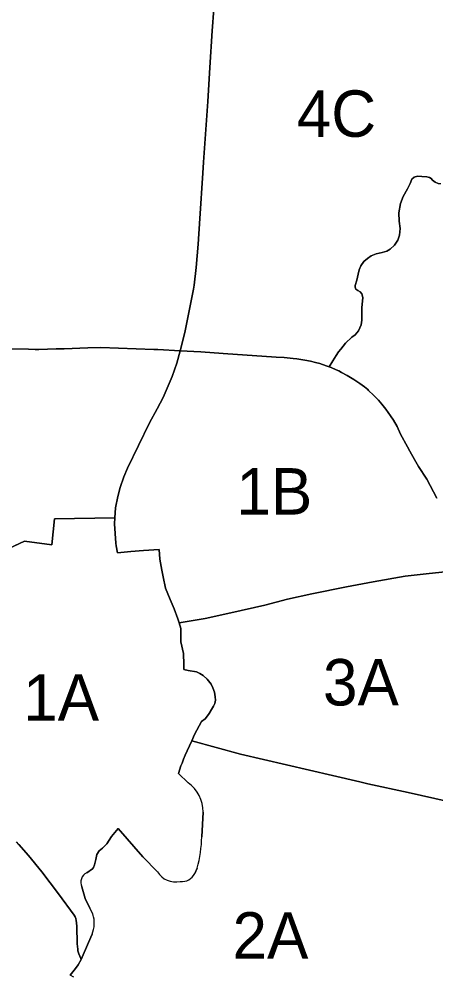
# Model space of a CAD drawing. Extents: x 152750 to 166250, y 378996 to 390000.
# Drawn here: x 161080 to 162877, y 382190 to 386288 of the extents above; entities that cross this region are included whole.
import ezdxf

# ---------------------------------------------------------------- set-up
doc = ezdxf.new("R2010")
doc.units = 0
doc.layers.add('BLT_Nummers', color=7, linetype='Continuous')
doc.layers.add('BLT_Shapes', color=7, linetype='Continuous')

msp = doc.modelspace()

# ---------------------------------------------------------------- linework, layer by layer
at = {"layer": 'BLT_Shapes'}
for p, q in [((161912.3, 386237.6), (161902.1, 386079.3)), ((161902.1, 386079.3), (161893.7, 385933.6)), ((161893.7, 385933.6), (161875.4, 385672.6)), ((162797.2, 385611.8), (162815.3, 385610.1)), ((162861.9, 385595), (162872.7, 385586.3)), ((162723.7, 385493.9), (162735, 385524.1)), ((162716, 385453.7), (162723.7, 385493.9)), ((161859.1, 385428.7), (161851.8, 385318.4)), ((162718.1, 385418.2), (162716, 385453.7)), ((162721.6, 385386.3), (162718.1, 385418.2)), ((162719, 385358.2), (162721.6, 385386.3)), ((162545.3, 385209.1), (162553.1, 385225.5)), ((162553.1, 385225.5), (162565.6, 385244.1)), ((162540.6, 385190.5), (162545.3, 385209.1)), ((161831.9, 385125.3), (161794.2, 384939.2)), ((162560.9, 385089), (162557, 385105)), ((162554.4, 384971.9), (162556.6, 384992.2)), ((161794.2, 384939.2), (161773.9, 384860.2)), ((162513.4, 384918.7), (162528.1, 384928.3)), ((161149.4, 384865.5), (161165.2, 384865.5)), ((161165.2, 384865.5), (161239.4, 384868)), ((161239.4, 384868), (161274.7, 384868.9)), ((161274.7, 384868.9), (161375.8, 384873)), ((161375.8, 384873), (161432.8, 384873.7)), ((162416, 384790.8), (162432.8, 384816.1)), ((162569.1, 384704.2), (162582.5, 384693.2)), ((162582.5, 384693.2), (162586.4, 384689.7)), ((162643.8, 384630.1), (162661.1, 384608.1)), ((162661.1, 384608.1), (162680.5, 384580.4)), ((162709, 384534.6), (162723.7, 384501.6)), ((162764.3, 384427.5), (162783.5, 384391.8)), ((161515.4, 384271.4), (161531.5, 384317.1)), ((161232.4, 384136.5), (161492.7, 384141)), ((161492.7, 384141), (161491, 384114.6)), ((160881.5, 383937.4), (161102.9, 384039.9)), ((161498.3, 384019.9), (161504.2, 383989.9)), ((161504.2, 383989.9), (161561.8, 383996.2)), ((161561.8, 383996.2), (161616.9, 383999.8)), ((161616.9, 383999.8), (161684, 384004.2)), ((162341.5, 383813.6), (162236.2, 383790.4)), ((161763.7, 383706), (161769.3, 383688.6)), ((161769.3, 383688.6), (161777.2, 383664.4)), ((161788.4, 383557.5), (161790.7, 383508.9)), ((161923.1, 383342.4), (161917.7, 383329.6)), ((161866.6, 383264.3), (161836, 383207.9)), ((161836, 383207.9), (161824.5, 383181.5)), ((161824.5, 383181.5), (162034.4, 383123.8)), ((161795.8, 383119.3), (161789.1, 383101.9)), ((161809.4, 383000.4), (161766.8, 383040)), ((161766.8, 383040), (161809.4, 383000.4)), ((162548.9, 383003.9), (162582.8, 382996)), ((162582.8, 382996), (162756.1, 382958.4)), ((161867.4, 382768.3), (161873.2, 382874.7)), ((161873.2, 382874.7), (161867.4, 382768.3)), ((161506.9, 382803.7), (161477.9, 382768.9)), ((161477.9, 382768.9), (161457.6, 382738)), ((161457.6, 382738), (161439.2, 382719.6)), ((161177.8, 382617.1), (161121.2, 382688.1)), ((161396.7, 382629.7), (161371.5, 382613.2)), ((161401.5, 382635.5), (161396.7, 382629.7)), ((161837.4, 382609.8), (161848, 382633)), ((161848, 382633), (161837.4, 382609.8)), ((161249.4, 382522.2), (161177.8, 382617.1)), ((161385.1, 382460.5), (161398.6, 382434.4)), ((161345.7, 382244.2), (161337.1, 382264.8)), ((161335.4, 382216.2), (161348, 382239.7)), ((161347.7, 382240.2), (161345.7, 382244.2)), ((161348, 382239.7), (161347.7, 382240.2)), ((161323.9, 382201.5), (161335.4, 382216.2))]:
    msp.add_line(p, q, dxfattribs=at)
for points in [[(161773.9, 384860.2), (161794.2, 384939.2), (161831.9, 385125.3), (161835, 385142.9), (161843.4, 385219.2), (161851.8, 385318.4), (161859.1, 385428.7), (161872.2, 385624.7), (161875.4, 385672.6), (161893.7, 385933.6), (161902.1, 386079.3), (161912.3, 386237.6), (161927.2, 386428.6), (161929.6, 386454.8), (161933.9, 386510.6)], [(161933.9, 386510.6), (161929.6, 386454.8), (161927.2, 386428.6), (161912.3, 386237.6)], [(161875.4, 385672.6), (161872.2, 385624.7), (161859.1, 385428.7)], [(162885.7, 385580.3), (162872.7, 385586.3), (162861.9, 385595), (162855.5, 385601), (162848.1, 385606.2), (162836.5, 385609.2), (162815.3, 385610.1), (162797.2, 385611.8), (162782, 385607.1), (162772.1, 385598.4), (162764.8, 385580.7), (162753.5, 385556.9), (162735, 385524.1), (162723.7, 385493.9), (162716, 385453.7), (162718.1, 385418.2), (162721.6, 385386.3), (162719, 385358.2), (162712.5, 385336.1), (162697.8, 385314.1), (162679.7, 385296.8), (162664.6, 385288.2), (162644.3, 385283.4), (162618.3, 385277), (162597.6, 385268.7), (162581.6, 385257.9), (162565.6, 385244.1), (162553.1, 385225.5), (162545.3, 385209.1), (162540.6, 385190.5), (162535.8, 385163.7), (162528.1, 385141.7), (162528.1, 385133.9), (162531.1, 385124.9), (162539.3, 385118.8), (162549.7, 385113.6), (162557, 385105), (162560.9, 385089), (162557.4, 385044.9), (162556.6, 384992.2), (162554.4, 384971.9), (162543.2, 384946.4), (162528.1, 384928.3), (162513.4, 384918.7), (162486.6, 384892.4), (162466.3, 384867.5), (162456.6, 384855.9), (162447.1, 384840.3), (162432.8, 384816.1), (162416, 384790.8)], [(162735, 385524.1), (162753.5, 385556.9), (162764.8, 385580.7), (162772.1, 385598.4)], [(162772.1, 385598.4), (162782, 385607.1), (162797.2, 385611.8)], [(162815.3, 385610.1), (162836.5, 385609.2), (162848.1, 385606.2), (162855.5, 385601), (162861.9, 385595)], [(162872.7, 385586.3), (162885.7, 385580.3), (162896.9, 385580.7)], [(162679.7, 385296.8), (162697.8, 385314.1), (162712.5, 385336.1), (162719, 385358.2)], [(161851.8, 385318.4), (161843.4, 385219.2), (161835, 385142.9), (161831.9, 385125.3)], [(162618.3, 385277), (162644.3, 385283.4), (162664.6, 385288.2), (162679.7, 385296.8)], [(162565.6, 385244.1), (162581.6, 385257.9), (162597.6, 385268.7), (162618.3, 385277)], [(162528.1, 385133.9), (162528.1, 385141.7), (162535.8, 385163.7), (162540.6, 385190.5)], [(162557, 385105), (162549.7, 385113.6), (162539.3, 385118.8), (162531.1, 385124.9), (162528.1, 385133.9)], [(162556.6, 384992.2), (162557.4, 385044.9), (162560.9, 385089)], [(162528.1, 384928.3), (162543.2, 384946.4), (162554.4, 384971.9)], [(162432.8, 384816.1), (162447.1, 384840.3), (162456.6, 384855.9), (162466.3, 384867.5), (162486.6, 384892.4), (162513.4, 384918.7)], [(160886.6, 384852.9), (160907.9, 384858.1), (160952.6, 384868.2), (160958.7, 384869.5), (161120.2, 384867.2), (161149.4, 384865.5)], [(161773.9, 384860.2), (161678.4, 384865.3), (161661.3, 384866.1), (161432.8, 384873.7), (161375.8, 384873), (161274.7, 384868.9), (161239.4, 384868), (161165.2, 384865.5), (161149.4, 384865.5), (161120.2, 384867.2), (160958.7, 384869.5)], [(161432.8, 384873.7), (161661.3, 384866.1), (161678.4, 384865.3), (161773.9, 384860.2)], [(161773.9, 384860.2), (161760.2, 384807.1), (161740.4, 384749.9), (161701.7, 384658.7), (161675.8, 384609.5), (161642.8, 384550.3), (161546.8, 384355.4), (161531.5, 384317.1), (161515.4, 384271.4), (161505.2, 384233.1), (161495.6, 384184), (161492.7, 384141)], [(161701.7, 384658.7), (161740.4, 384749.9), (161760.2, 384807.1), (161773.9, 384860.2)], [(162416, 384790.8), (162403.9, 384795.4), (162375.6, 384804.7), (162358.1, 384809.9), (162335.4, 384815), (162311.7, 384820), (162294.6, 384822.8), (162276.3, 384825.2), (162261.4, 384826.7), (162222.9, 384830.4), (162188.6, 384832.8), (161959.3, 384848.5), (161863.8, 384855.4), (161773.9, 384860.2)], [(161773.9, 384860.2), (161863.8, 384855.4), (161959.3, 384848.5), (162188.6, 384832.8), (162222.9, 384830.4)], [(162222.9, 384830.4), (162261.4, 384826.7), (162276.3, 384825.2)], [(162276.3, 384825.2), (162294.6, 384822.8), (162311.7, 384820)], [(162311.7, 384820), (162335.4, 384815), (162358.1, 384809.9), (162375.6, 384804.7), (162403.9, 384795.4), (162416, 384790.8)], [(162880.5, 384225.3), (162836.7, 384307.9), (162801.7, 384361.3), (162783.5, 384391.8), (162764.3, 384427.5), (162754.2, 384446.3), (162723.7, 384501.6), (162709, 384534.6), (162693.3, 384561), (162680.5, 384580.4), (162661.1, 384608.1), (162643.8, 384630.1), (162628.7, 384647.6), (162607.8, 384669.2), (162586.4, 384689.7), (162582.5, 384693.2), (162569.1, 384704.2), (162548.2, 384719.5), (162522.2, 384737), (162493.7, 384753.9), (162470.2, 384766.6), (162457.5, 384773.3), (162446, 384778.3), (162425.1, 384787.4), (162416, 384790.8)], [(162416, 384790.8), (162425.1, 384787.4), (162446, 384778.3), (162457.5, 384773.3), (162470.2, 384766.6)], [(162470.2, 384766.6), (162493.7, 384753.9), (162522.2, 384737)], [(162522.2, 384737), (162548.2, 384719.5), (162569.1, 384704.2)], [(162586.4, 384689.7), (162607.8, 384669.2), (162628.7, 384647.6), (162643.8, 384630.1)], [(161642.8, 384550.3), (161675.8, 384609.5), (161701.7, 384658.7)], [(162680.5, 384580.4), (162693.3, 384561), (162709, 384534.6)], [(161531.5, 384317.1), (161546.8, 384355.4), (161642.8, 384550.3)], [(162723.7, 384501.6), (162754.2, 384446.3), (162764.3, 384427.5)], [(162783.5, 384391.8), (162801.7, 384361.3), (162836.7, 384307.9), (162880.5, 384225.3)], [(161492.7, 384141), (161495.6, 384184), (161505.2, 384233.1), (161515.4, 384271.4)], [(161492.7, 384141), (161232.4, 384136.5), (161220.8, 384025.3), (161102.9, 384039.9), (160881.5, 383937.4), (160937.5, 383821.9)], [(161102.9, 384039.9), (161220.8, 384025.3), (161232.4, 384136.5)], [(161504.2, 383989.9), (161498.3, 384019.9), (161496.7, 384032.6), (161491, 384114.6), (161492.7, 384141)], [(161491, 384114.6), (161496.7, 384032.6), (161498.3, 384019.9)], [(161769.3, 383688.6), (161763.7, 383706), (161748.4, 383749.8), (161730.9, 383789.6), (161711.7, 383838.6), (161700.4, 383887.4), (161694.9, 383916.2), (161686.9, 383962.6), (161684, 384004.2), (161616.9, 383999.8), (161561.8, 383996.2), (161504.2, 383989.9)], [(161684, 384004.2), (161686.9, 383962.6), (161694.9, 383916.2), (161700.4, 383887.4), (161711.7, 383838.6), (161730.9, 383789.6)], [(162606.3, 383864.8), (162744, 383890), (162833.8, 383899.6), (162928.6, 383909.3), (163035.7, 383918.7), (163036.4, 383918.8)], [(162928.6, 383909.3), (162833.8, 383899.6), (162744, 383890), (162606.3, 383864.8)], [(161769.3, 383688.6), (161882.4, 383708.2), (161992.6, 383731.4), (162138.5, 383764.3), (162236.2, 383790.4), (162341.5, 383813.6), (162491.3, 383843.6), (162606.3, 383864.8)], [(162606.3, 383864.8), (162491.3, 383843.6), (162341.5, 383813.6)], [(161730.9, 383789.6), (161748.4, 383749.8), (161763.7, 383706)], [(162236.2, 383790.4), (162138.5, 383764.3), (161992.6, 383731.4), (161882.4, 383708.2), (161769.3, 383688.6)], [(161824.5, 383181.5), (161836, 383207.9), (161866.6, 383264.3), (161881.5, 383275.6), (161887.4, 383283.6), (161899.1, 383298.2), (161909.6, 383315.7), (161917.7, 383329.6), (161923.1, 383342.4), (161926.4, 383355.9), (161925.7, 383370.9), (161922.4, 383390.2), (161915.5, 383409.6), (161907.7, 383425.1), (161890.6, 383445.9), (161873.5, 383462.1), (161858.7, 383470.4), (161845.3, 383477.8), (161808.3, 383483.9), (161789.9, 383488.6), (161790.7, 383508.9), (161788.4, 383557.5), (161777.3, 383606.9), (161777.2, 383637), (161777.2, 383664.4), (161769.3, 383688.6)], [(161777.2, 383664.4), (161777.2, 383637), (161777.3, 383606.9), (161788.4, 383557.5)], [(161790.7, 383508.9), (161789.9, 383488.6), (161808.3, 383483.9), (161845.3, 383477.8), (161858.7, 383470.4)], [(161858.7, 383470.4), (161873.5, 383462.1), (161890.6, 383445.9), (161907.7, 383425.1)], [(161907.7, 383425.1), (161915.5, 383409.6), (161922.4, 383390.2)], [(161922.4, 383390.2), (161925.7, 383370.9), (161926.4, 383355.9), (161923.1, 383342.4)], [(161917.7, 383329.6), (161909.6, 383315.7), (161899.1, 383298.2), (161887.4, 383283.6)], [(161887.4, 383283.6), (161881.5, 383275.6), (161866.6, 383264.3)], [(161766.8, 383040), (161777.5, 383072.9), (161782.3, 383085.5), (161789.1, 383101.9), (161795.8, 383119.3), (161804.5, 383138.7), (161824.5, 383181.5)], [(161824.5, 383181.5), (161804.5, 383138.7), (161795.8, 383119.3)], [(162548.9, 383003.9), (162430.3, 383031.7), (162034.4, 383123.8), (161824.5, 383181.5)], [(162034.4, 383123.8), (162430.3, 383031.7), (162548.9, 383003.9)], [(161789.1, 383101.9), (161782.3, 383085.5), (161777.5, 383072.9), (161766.8, 383040)], [(163124.9, 382876.6), (163107.8, 382880.2), (163100.9, 382881.7), (162756.1, 382958.4), (162582.8, 382996), (162548.9, 383003.9)], [(162756.1, 382958.4), (163100.9, 382881.7), (163107.8, 382880.2), (163124.9, 382876.6)], [(161371.5, 382613.2), (161396.7, 382629.7), (161401.5, 382635.5), (161405.4, 382647.1), (161410.2, 382670.3), (161415, 382691.6), (161425.7, 382708), (161439.2, 382719.6), (161457.6, 382738), (161477.9, 382768.9), (161506.9, 382803.7)], [(161506.9, 382803.7), (161614.1, 382681.3), (161676, 382617.5)], [(161676, 382617.5), (161614.1, 382681.3), (161506.9, 382803.7)], [(161121.2, 382688.1), (161079.7, 382735.3), (161069.1, 382746.3)], [(161079.7, 382735.3), (161121.2, 382688.1), (161177.8, 382617.1), (161249.4, 382522.2), (161317.4, 382430.5), (161321.2, 382423), (161324.1, 382415.6), (161326.5, 382408.3), (161327.8, 382397.1), (161328.5, 382381.2), (161330.7, 382308.6), (161331.8, 382294.5), (161332.9, 382285.8), (161333.6, 382277.8), (161337.1, 382264.8), (161345.7, 382244.2), (161347.7, 382240.2), (161348, 382239.7)], [(161439.2, 382719.6), (161425.7, 382708), (161415, 382691.6), (161410.2, 382670.3)], [(161410.2, 382670.3), (161405.4, 382647.1), (161401.5, 382635.5)], [(161398.6, 382434.4), (161385.1, 382460.5), (161364.8, 382503), (161350.3, 382552.3)], [(161350.3, 382552.3), (161364.8, 382503), (161385.1, 382460.5)], [(161328.5, 382381.2), (161327.8, 382397.1), (161326.5, 382408.3), (161324.1, 382415.6), (161321.2, 382423), (161317.4, 382430.5), (161249.4, 382522.2)], [(161332.9, 382285.8), (161331.8, 382294.5), (161330.7, 382308.6), (161328.5, 382381.2)], [(161348, 382239.7), (161379.3, 382312.5), (161394.7, 382348.3)], [(161394.7, 382348.3), (161379.3, 382312.5), (161348, 382239.7)], [(161337.1, 382264.8), (161333.6, 382277.8), (161332.9, 382285.8)], [(161348, 382239.7), (161335.4, 382216.2), (161323.9, 382201.5), (161300.4, 382172.7)], [(161316.6, 382163.2), (161300.4, 382172.7), (161323.9, 382201.5)]]:
    msp.add_lwpolyline(points, dxfattribs=at)
for centre, radius, start, end in [((161716.4, 382874.2), 156.7, 0.1845, 53.6273), ((161716.4, 382874.2), 156.7, 0.1845, 53.6273), ((161303.5, 382779.8), 564, 344.9103, 358.8366), ((161303.5, 382779.8), 564, 344.9103, 358.8366), ((161392.6, 382571.7), 46.6, 116.9048, 204.6133), ((161392.6, 382571.7), 46.6, 116.9048, 204.6133), ((161753.9, 382664.6), 91, 211.1362, 283.1286), ((161753.9, 382664.6), 91, 211.1362, 283.1286), ((161782.4, 382636.6), 61.1, 262.6062, 334.017), ((161782.4, 382636.6), 61.1, 262.6062, 334.017), ((161280.4, 382396.6), 124.1, 337.1236, 17.732), ((161280.4, 382396.6), 124.1, 337.1236, 17.732)]:
    msp.add_arc(centre, radius, start, end, dxfattribs=at)

# ---------------------------------------------------------------- texts
at = {"layer": 'BLT_Nummers'}
for s, p in [('4C', (162276.7, 385780.9)), ('1B', (162016.6, 384155)), ('3A', (162389.6, 383333.2)), ('1A', (161097.7, 383267.7)), ('2A', (161999.7, 382243.3))]:
    msp.add_text(s, height=200, dxfattribs=at).set_placement(p)

doc.saveas('drawing.dxf')
